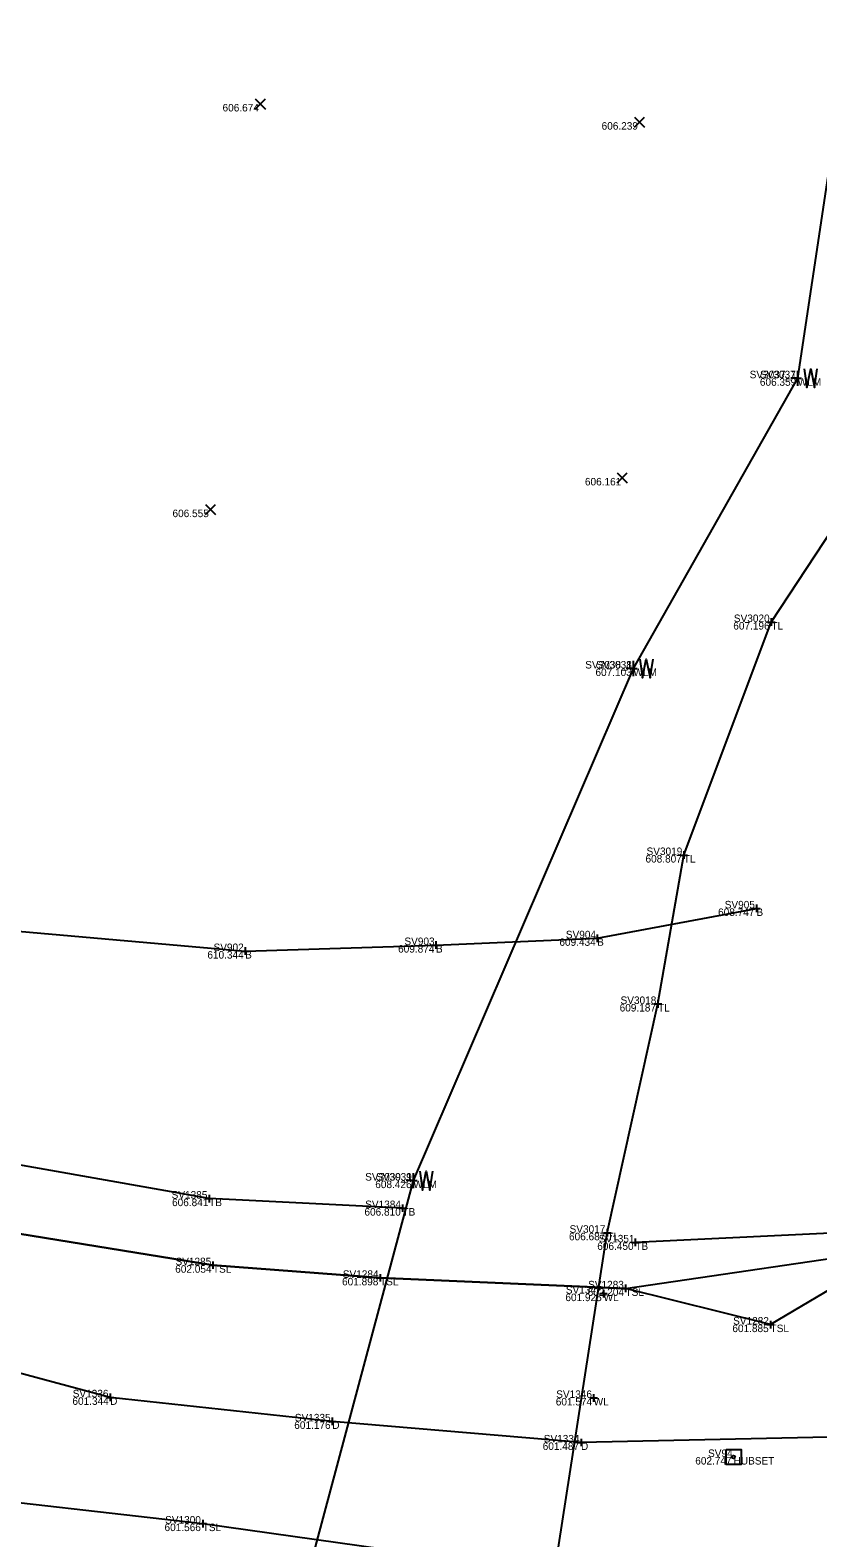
# Model space of a CAD drawing. Extents: x -2 to 1979875, y -2 to 232027.
# Drawn here: x 1978698.9 to 1978751.3, y 231261.4 to 231361.7 of the extents above; entities that cross this region are included whole.
import ezdxf

# ---------------------------------------------------------------- set-up
doc = ezdxf.new("R2010")
doc.units = 0
for name, color, linetype in [('_CIVIL_CONSTRUCTION', 7, 'Continuous'), ('DR_X_Ditch', 7, 'Continuous'), ('GE_P_Alignment', 7, 'Continuous'), ('GE_P_Alignment_1000_Curve_Data', 7, 'Continuous'), ('GE_X_Alignment', 7, 'Continuous'), ('GE_X_Alignment_100_Curve_Data', 7, 'Continuous'), ('GE_X_Alignment_100_Stations', 7, 'Continuous'), ('HY_X_Water_Edge', 7, 'Continuous'), ('SV_P_Control_Cells_Set', 7, 'Continuous'), ('SV_X_Random_Point', 7, 'Continuous'), ('SV_X_Toe_of_Slope', 7, 'Continuous'), ('SV_X_Top_of_Bank', 7, 'Continuous'), ('UT_X_Water', 7, 'Continuous'), ('UT_X_Water_Cells', 7, 'Continuous')]:
    doc.layers.add(name, color=color, linetype=linetype)

msp = doc.modelspace()

# ---------------------------------------------------------------- linework, layer by layer
at = {"layer": 'DR_X_Ditch'}
msp.add_lwpolyline([(1978761.84, 231269.6), (1978754.07, 231268.15), (1978735.57, 231267.76), (1978719.02, 231269.16), (1978704.24, 231270.76), (1978691.44, 231274.18), (1978676.78, 231277.11), (1978662.93, 231282.94), (1978648.1, 231287.83), (1978629.39, 231288.45)], dxfattribs=at)
at = {"layer": 'GE_P_Alignment'}
msp.add_lwpolyline([(1978641.05, 231311), (1978655.14, 231308.93), (1978670.95, 231306.25), (1978685.28, 231304.31), (1978697.36, 231301.85), (1978713.22, 231300.45), (1978725.92, 231300.85), (1978736.64, 231301.3), (1978747.24, 231303.29)], dxfattribs=at)
at = {"layer": 'GE_P_Alignment_1000_Curve_Data'}
msp.add_lwpolyline([(1978733.12, 231254.65), (1978737.32, 231281.71), (1978740.69, 231296.93), (1978742.41, 231306.84), (1978748.23, 231322.34), (1978755.32, 231333.12), (1978758.78, 231344.16), (1978763.01, 231368.43), (1978764.4, 231379.72), (1978765.86, 231395.08), (1978767.24, 231417.34), (1978767.1, 231431.46), (1978767.53, 231441.08), (1978768.45, 231451.79), (1978770.87, 231461.5), (1978774, 231474.92), (1978775.89, 231489.03), (1978776.9, 231504.34), (1978777.94, 231514.65)], dxfattribs=at)
at = {"layer": 'GE_X_Alignment_100_Curve_Data'}
for p, q in [((1978749.74, 231338.56), (1978750.24, 231338.56)), ((1978749.99, 231338.81), (1978749.99, 231338.31)), ((1978749.99, 231338.56), (1978749.99, 231338.56)), ((1978747.98, 231322.34), (1978748.48, 231322.34)), ((1978748.23, 231322.59), (1978748.23, 231322.09)), ((1978748.23, 231322.34), (1978748.23, 231322.34)), ((1978738.81, 231319.25), (1978739.31, 231319.25)), ((1978739.06, 231319.5), (1978739.06, 231319)), ((1978739.06, 231319.25), (1978739.06, 231319.25)), ((1978742.41, 231307.09), (1978742.41, 231306.59)), ((1978742.16, 231306.84), (1978742.66, 231306.84)), ((1978742.41, 231306.84), (1978742.41, 231306.84)), ((1978746.99, 231303.29), (1978747.49, 231303.29)), ((1978747.24, 231303.54), (1978747.24, 231303.04)), ((1978747.24, 231303.29), (1978747.24, 231303.29)), ((1978725.92, 231301.1), (1978725.92, 231300.6)), ((1978736.39, 231301.3), (1978736.89, 231301.3)), ((1978736.64, 231301.55), (1978736.64, 231301.05)), ((1978736.64, 231301.3), (1978736.64, 231301.3)), ((1978712.97, 231300.45), (1978713.47, 231300.45)), ((1978713.22, 231300.7), (1978713.22, 231300.2)), ((1978713.22, 231300.45), (1978713.22, 231300.45)), ((1978725.67, 231300.85), (1978726.17, 231300.85)), ((1978725.92, 231300.85), (1978725.92, 231300.85)), ((1978740.44, 231296.93), (1978740.94, 231296.93)), ((1978740.69, 231297.18), (1978740.69, 231296.68)), ((1978740.69, 231296.93), (1978740.69, 231296.93)), ((1978724.17, 231285.18), (1978724.67, 231285.18)), ((1978724.42, 231285.43), (1978724.42, 231284.93)), ((1978724.42, 231285.18), (1978724.42, 231285.18)), ((1978710.58, 231283.98), (1978711.08, 231283.98)), ((1978710.83, 231284.23), (1978710.83, 231283.73)), ((1978710.83, 231283.98), (1978710.83, 231283.98)), ((1978723.44, 231283.35), (1978723.94, 231283.35)), ((1978723.69, 231283.6), (1978723.69, 231283.1)), ((1978723.69, 231283.35), (1978723.69, 231283.35)), ((1978737.32, 231281.96), (1978737.32, 231281.46)), ((1978737.07, 231281.71), (1978737.57, 231281.71)), ((1978737.32, 231281.71), (1978737.32, 231281.71)), ((1978738.93, 231281.07), (1978739.43, 231281.07)), ((1978739.18, 231281.32), (1978739.18, 231280.82)), ((1978739.18, 231281.07), (1978739.18, 231281.07)), ((1978711.08, 231279.8), (1978711.08, 231279.3)), ((1978710.83, 231279.55), (1978711.33, 231279.55)), ((1978711.08, 231279.55), (1978711.08, 231279.55)), ((1978722.2, 231278.96), (1978722.2, 231278.46)), ((1978721.95, 231278.71), (1978722.45, 231278.71)), ((1978722.2, 231278.71), (1978722.2, 231278.71)), ((1978737.07, 231277.91), (1978737.07, 231277.41)), ((1978738.28, 231278.01), (1978738.78, 231278.01)), ((1978738.53, 231278.26), (1978738.53, 231277.76)), ((1978738.53, 231278.01), (1978738.53, 231278.01)), ((1978736.82, 231277.66), (1978737.32, 231277.66)), ((1978737.07, 231277.66), (1978737.07, 231277.66)), ((1978748.18, 231275.85), (1978748.18, 231275.35)), ((1978747.93, 231275.6), (1978748.43, 231275.6)), ((1978748.18, 231275.6), (1978748.18, 231275.6)), ((1978704.24, 231271.01), (1978704.24, 231270.51)), ((1978736.41, 231270.97), (1978736.41, 231270.47)), ((1978703.99, 231270.76), (1978704.49, 231270.76)), ((1978704.24, 231270.76), (1978704.24, 231270.76)), ((1978736.16, 231270.72), (1978736.66, 231270.72)), ((1978736.41, 231270.72), (1978736.41, 231270.72)), ((1978718.77, 231269.16), (1978719.27, 231269.16)), ((1978719.02, 231269.41), (1978719.02, 231268.91)), ((1978719.02, 231269.16), (1978719.02, 231269.16)), ((1978735.57, 231268.01), (1978735.57, 231267.51)), ((1978735.32, 231267.76), (1978735.82, 231267.76)), ((1978735.57, 231267.76), (1978735.57, 231267.76)), ((1978710.15, 231262.36), (1978710.65, 231262.36)), ((1978710.4, 231262.61), (1978710.4, 231262.11)), ((1978710.4, 231262.36), (1978710.4, 231262.36))]:
    msp.add_line(p, q, dxfattribs=at)
at = {"layer": 'HY_X_Water_Edge'}
for points in [[(1978627.99, 231296.51), (1978640.32, 231295.77), (1978658.46, 231291.26), (1978670.01, 231286.08), (1978680, 231283.02), (1978693.83, 231282.34), (1978711.08, 231279.55), (1978722.2, 231278.71), (1978738.53, 231278.01), (1978757.26, 231280.76)], [(1978631.82, 231277.19), (1978672.58, 231269.51), (1978692.09, 231264.45), (1978710.4, 231262.36), (1978725.37, 231260.25)]]:
    msp.add_lwpolyline(points, dxfattribs=at)
at = {"layer": 'SV_P_Control_Cells_Set'}
msp.add_lwpolyline([(1978745.23, 231267.28), (1978746.22, 231267.28), (1978746.22, 231266.29), (1978745.23, 231266.29), (1978745.23, 231267.28)], dxfattribs=at)
msp.add_lwpolyline([(1978745.23, 231267.28), (1978746.22, 231267.28), (1978746.22, 231266.29), (1978745.23, 231266.29), (1978745.23, 231267.28)], dxfattribs=at)
msp.add_circle((1978745.72, 231266.79), 0.1, dxfattribs=at)
msp.add_circle((1978745.72, 231266.79), 0.1, dxfattribs=at)
at = {"layer": 'SV_X_Random_Point'}
for p, q in [((1978713.9, 231356.47), (1978714.57, 231357.14)), ((1978713.9, 231357.14), (1978714.57, 231356.47)), ((1978739.12, 231355.27), (1978739.79, 231355.93)), ((1978739.12, 231355.93), (1978739.79, 231355.27)), ((1978737.97, 231331.6), (1978738.64, 231332.26)), ((1978737.97, 231332.26), (1978738.64, 231331.6)), ((1978710.59, 231329.49), (1978711.26, 231330.15)), ((1978710.59, 231330.15), (1978711.26, 231329.49))]:
    msp.add_line(p, q, dxfattribs=at)
at = {"layer": 'SV_X_Toe_of_Slope'}
for points in [[(1978763.37, 231281.56), (1978757.26, 231280.76), (1978753.76, 231278.9), (1978748.18, 231275.6), (1978738.53, 231278.01), (1978722.2, 231278.71), (1978711.08, 231279.55), (1978693.83, 231282.34), (1978680, 231283.02), (1978670.01, 231286.08), (1978658.46, 231291.26), (1978640.32, 231295.77), (1978627.99, 231296.51)], [(1978631.82, 231277.19), (1978640.95, 231277.19), (1978647.86, 231282.13), (1978659.87, 231277.69), (1978667.49, 231272.24), (1978672.58, 231269.51), (1978692.09, 231264.45), (1978710.4, 231262.36), (1978725.37, 231260.25), (1978739.36, 231256.71), (1978742.04, 231254.08), (1978741.88, 231245.47), (1978742.32, 231240.48), (1978743.74, 231236.89), (1978745.95, 231227.45)]]:
    msp.add_lwpolyline(points, dxfattribs=at)
at = {"layer": 'SV_X_Top_of_Bank'}
for points in [[(1978723.69, 231283.35), (1978710.83, 231283.98), (1978688.99, 231287.85), (1978673.17, 231289.24), (1978657.94, 231297.38), (1978644.93, 231301.22), (1978630.36, 231307.3)], [(1978761.65, 231284.12), (1978754.48, 231281.79), (1978739.18, 231281.07)]]:
    msp.add_lwpolyline(points, dxfattribs=at)
at = {"layer": 'UT_X_Water'}
msp.add_lwpolyline([(1978712.49, 231209.97), (1978714.81, 231240.89), (1978716.64, 231256.08), (1978724.42, 231285.18), (1978739.06, 231319.25), (1978749.99, 231338.56), (1978758.98, 231398.4), (1978764.29, 231459.71)], dxfattribs=at)
at = {"layer": 'UT_X_Water_Cells'}
for p, q in [((1978749.99, 231338.06), (1978749.99, 231339.06)), ((1978749.99, 231338.56), (1978749.52, 231338.56)), ((1978739.06, 231319.25), (1978738.58, 231319.25)), ((1978739.06, 231318.75), (1978739.06, 231319.75)), ((1978724.42, 231285.18), (1978723.94, 231285.18)), ((1978724.42, 231284.68), (1978724.42, 231285.68))]:
    msp.add_line(p, q, dxfattribs=at)
for points in [[(1978750.42, 231339.19), (1978750.6, 231337.94), (1978750.85, 231339.19), (1978751.1, 231337.94), (1978751.29, 231339.19)], [(1978739.48, 231319.88), (1978739.67, 231318.63), (1978739.91, 231319.88), (1978740.16, 231318.63), (1978740.36, 231319.88)], [(1978724.84, 231285.8), (1978725.03, 231284.55), (1978725.27, 231285.8), (1978725.52, 231284.55), (1978725.72, 231285.8)]]:
    msp.add_lwpolyline(points, dxfattribs=at)

# ---------------------------------------------------------------- texts
at = {"layer": '_CIVIL_CONSTRUCTION'}
for s, p in [('606.674', (1978711.72, 231356.31)), ('606.239', (1978736.94, 231355.1)), ('606.359', (1978747.47, 231338.06)), ('606.359', (1978747.47, 231338.06)), ('606.161', (1978735.83, 231331.43)), ('606.555', (1978708.39, 231329.32)), ('607.196', (1978745.7, 231321.84)), ('607.103', (1978736.53, 231318.75)), ('607.103', (1978736.53, 231318.75)), ('608.807', (1978739.86, 231306.34)), ('608.747', (1978744.69, 231302.79)), ('609.434', (1978734.13, 231300.8)), ('610.344', (1978710.71, 231299.95)), ('609.874', (1978723.4, 231300.35)), ('609.187', (1978738.14, 231296.43)), ('608.426', (1978721.88, 231284.68)), ('608.426', (1978721.88, 231284.68)), ('606.841', (1978708.36, 231283.48)), ('606.810', (1978721.16, 231282.85)), ('606.687', (1978734.77, 231281.21)), ('606.450', (1978736.65, 231280.57)), ('602.054', (1978708.57, 231279.05)), ('601.898', (1978719.67, 231278.21)), ('602.204', (1978736.01, 231277.51)), ('601.925', (1978734.53, 231277.16)), ('601.885', (1978745.64, 231275.1)), ('601.344', (1978701.73, 231270.26)), ('601.574', (1978733.89, 231270.22)), ('601.176', (1978716.49, 231268.66)), ('601.487', (1978733.02, 231267.26)), ('602.747', (1978743.17, 231266.29)), ('602.747', (1978743.17, 231266.29)), ('601.566', (1978707.86, 231261.86))]:
    msp.add_text(s, height=0.5, dxfattribs=at).set_placement(p)
at = {"layer": 'GE_X_Alignment'}
for s, p in [('SV3037_1', (1978746.79, 231338.56)), ('SV3037', (1978747.48, 231338.56)), ('SV3020', (1978745.74, 231322.34)), ('SV3038_1', (1978735.85, 231319.25)), ('SV3038', (1978736.57, 231319.25)), ('SV3019', (1978739.93, 231306.84)), ('SV905', (1978745.13, 231303.29)), ('SV902', (1978711.12, 231300.45)), ('SV903', (1978723.82, 231300.85)), ('SV904', (1978734.56, 231301.3)), ('SV3018', (1978738.2, 231296.93)), ('SV3039_1', (1978721.21, 231285.18)), ('SV3039', (1978721.93, 231285.18)), ('SV1385', (1978708.33, 231283.98)), ('SV1384', (1978721.21, 231283.35)), ('SV3017', (1978734.81, 231281.71)), ('SV1351', (1978736.75, 231281.07)), ('SV1285', (1978708.59, 231279.55)), ('SV1284', (1978719.72, 231278.71)), ('SV1347', (1978734.56, 231277.66)), ('SV1283', (1978736.04, 231278.01)), ('SV1282', (1978745.69, 231275.6)), ('SV1336', (1978701.75, 231270.76)), ('SV1346', (1978733.92, 231270.72)), ('SV1335', (1978716.53, 231269.16)), ('SV1334', (1978733.09, 231267.76)), ('SV94', (1978744.02, 231266.79)), ('SV94', (1978744.02, 231266.79)), ('SV1300', (1978707.9, 231262.36))]:
    msp.add_text(s, height=0.5, dxfattribs=at).set_placement(p)
at = {"layer": 'GE_X_Alignment_100_Stations'}
for s, p in [('WL', (1978749.99, 231338.06)), ('WLM', (1978749.99, 231338.06)), ('TL', (1978748.23, 231321.84)), ('WL', (1978739.06, 231318.75)), ('WLM', (1978739.06, 231318.75)), ('TL', (1978742.41, 231306.34)), ('B', (1978747.24, 231302.79)), ('B', (1978736.64, 231300.8)), ('B', (1978713.22, 231299.95)), ('B', (1978725.92, 231300.35)), ('TL', (1978740.69, 231296.43)), ('WL', (1978724.42, 231284.68)), ('WLM', (1978724.42, 231284.68)), ('TB', (1978710.83, 231283.48)), ('TB', (1978723.69, 231282.85)), ('TL', (1978737.32, 231281.21)), ('TB', (1978739.18, 231280.57)), ('TSL', (1978711.08, 231279.05)), ('TSL', (1978722.2, 231278.21)), ('TSL', (1978738.53, 231277.51)), ('WL', (1978737.07, 231277.16)), ('TSL', (1978748.18, 231275.1)), ('D', (1978704.24, 231270.26)), ('WL', (1978736.41, 231270.22)), ('D', (1978719.02, 231268.66)), ('D', (1978735.57, 231267.26)), ('HUBSET', (1978745.72, 231266.29)), ('HUBSET', (1978745.72, 231266.29)), ('TSL', (1978710.4, 231261.86))]:
    msp.add_text(s, height=0.5, dxfattribs=at).set_placement(p)

doc.saveas('drawing.dxf')
